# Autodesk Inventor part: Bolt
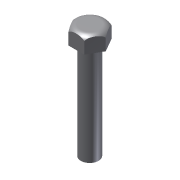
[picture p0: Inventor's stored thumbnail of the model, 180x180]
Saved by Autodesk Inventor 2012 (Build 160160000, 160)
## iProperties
Created: 2009-05
Part Number: Bolt
Document SubType Name: Modeling
Designer: Sham
Density: 1 g/cm^3
Material: Default
Author: Sham
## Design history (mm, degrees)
sketch "Sketch1"
  geometry: L1 (4, 0)-(2, -3.464); L2 (2, -3.464)-(-2, -3.464); L3 (-2, -3.464)-(-4, 0); L4 (-4, 0)-(-2, 3.464); L5 (-2, 3.464)-(2, 3.464); L6 (2, 3.464)-(4, 0); 1 further point
  constraints: 12 end point, 13 other
  dimensions: "d0" = 8 distance of L1.start L3.end
extrude "Extrusion1" new body sketch "Sketch1" distance "d1" = 4; taper "d2" = 0 deg
sketch "Sketch2"
  geometry: C1 r 2.25 at (0.082, 0)
  constraints: 1 centre point
  dimensions: "d3" = 4.5 diameter of C1
extrude "Extrusion2" join sketch "Sketch2" distance "d4" = 25; taper "d5" = 0 deg
sketch "Sketch3"
  geometry: L1 (0, -30.841)-(0, 10.046) reference; A1 r 1.88 centre (-2.337, 2.123) between (-2.442, 4) and (-4, 3)
  constraints: 2 point on circle, 1 centre point
revolve "Revolution1" sketch "Sketch3" stored, may be unused: angle "d7" = 90 deg
body "Solid1"
other parameters: "d6" = 90 deg
